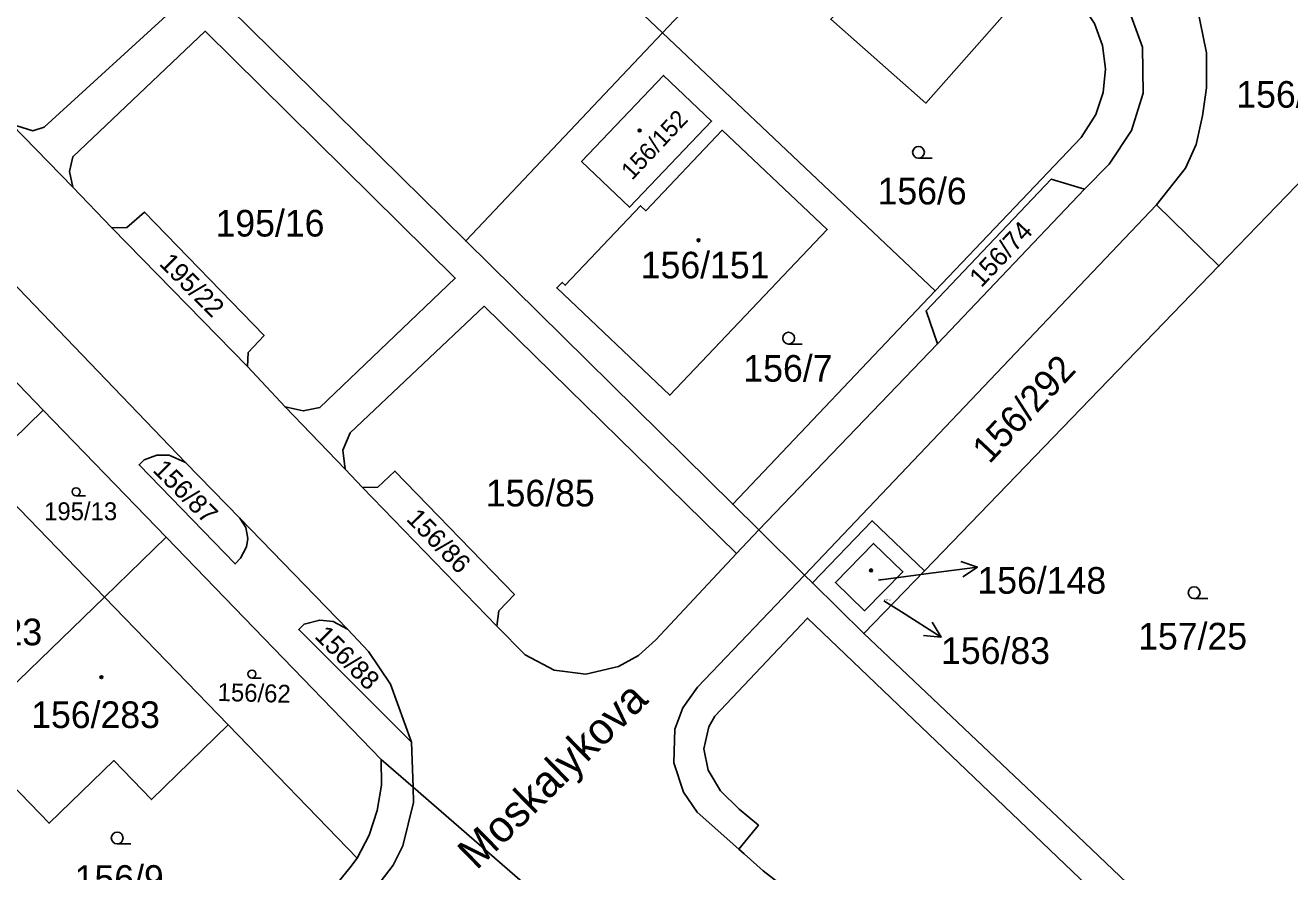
# Model space of a CAD drawing. Extents: x -598233 to -596890, y -1157848 to -1156431.
# Drawn here: x -597711.3 to -597630.6, y -1156695.2 to -1156641.2 of the extents above; entities that cross this region are included whole.
import ezdxf

# ---------------------------------------------------------------- set-up
doc = ezdxf.new("R2010")
doc.units = 0
for name, color, linetype in [('Level 1', 7, 'Continuous'), ('Level 11', 7, 'Continuous'), ('Level 4', 7, 'Continuous'), ('Level 5', 7, 'Continuous'), ('Level 57', 7, 'Continuous'), ('Level 60', 7, 'Continuous')]:
    doc.layers.add(name, color=color, linetype=linetype)

msp = doc.modelspace()

# ---------------------------------------------------------------- linework, layer by layer
at = {"layer": 'Level 1'}
for points in [[(-597670.61, -1156641.68), (-597688.79, -1156624.46)], [(-597657.3, -1156624.49), (-597643.05, -1156637.18), (-597641.03, -1156639.75), (-597639.99, -1156642.6), (-597639.94, -1156645.54), (-597640.68, -1156647.91), (-597642.12, -1156650.07), (-597643.69, -1156651.66)], [(-597712.16, -1156647.52), (-597710.81, -1156647.93), (-597710.09, -1156647.7), (-597701.55, -1156639.92), (-597715.07, -1156627.01), (-597722.85, -1156634.48), (-597723.06, -1156635.3), (-597722.83, -1156636.51)], [(-597657.42, -1156627.76), (-597670.61, -1156641.68)], [(-597653.21, -1156658.15), (-597643.9, -1156648.36), (-597642.97, -1156646.9), (-597642.49, -1156645.48), (-597642.34, -1156643.98), (-597642.53, -1156642.5), (-597643.05, -1156641.09), (-597643.87, -1156639.83), (-597656.51, -1156628.57), (-597657.42, -1156627.76)], [(-597647.47, -1156638.99), (-597653.81, -1156646.17), (-597659.88, -1156640.82), (-597659.54, -1156640.45), (-597662.02, -1156638.26), (-597656, -1156631.44), (-597647.47, -1156638.99)], [(-597639.1, -1156652.66), (-597637.24, -1156650.31), (-597636.57, -1156648.8), (-597636.16, -1156646.98), (-597635.89, -1156645.2), (-597635.91, -1156642.95), (-597636.5, -1156640.05), (-597637.79, -1156637.25), (-597639.98, -1156634.55), (-597640.57, -1156633.94)], [(-597700.93, -1156637.45), (-597694.23, -1156644.06), (-597683.18, -1156654.96)], [(-597694.71, -1156665.55), (-597693.55, -1156665.81), (-597692.48, -1156665.59), (-597683.84, -1156657.34), (-597699.81, -1156641.58), (-597708.26, -1156649.59), (-597708.46, -1156650.53), (-597708.25, -1156651.53)], [(-597670.61, -1156641.68), (-597683.18, -1156654.96)], [(-597653.21, -1156658.15), (-597670.61, -1156641.68)], [(-597675.78, -1156649.9), (-597670.55, -1156644.4), (-597667.49, -1156647.31), (-597672.72, -1156652.81), (-597675.78, -1156649.9)], [(-597635.11, -1156656.56), (-597624, -1156645.06)], [(-597708.25, -1156651.53), (-597712.16, -1156647.52)], [(-597666.8, -1156647.9), (-597660.1, -1156654.23), (-597670.16, -1156664.81), (-597677.37, -1156657.96), (-597677.02, -1156657.61), (-597676.83, -1156657.79), (-597672.02, -1156652.72), (-597671.69, -1156653.04), (-597666.8, -1156647.9)], [(-597643.69, -1156651.66), (-597645.81, -1156651.01), (-597653.8, -1156659.42), (-597653.07, -1156661.53)], [(-597708.25, -1156651.53), (-597705.77, -1156654.13)], [(-597653.07, -1156661.53), (-597643.69, -1156651.66)], [(-597661.55, -1156676.28), (-597639.1, -1156652.66)], [(-597639.1, -1156652.66), (-597635.11, -1156656.56)], [(-597705.77, -1156654.13), (-597704.81, -1156654.11), (-597703.68, -1156653.12), (-597696.04, -1156660.99), (-597697.06, -1156662.08), (-597697.1, -1156662.97)], [(-597705.77, -1156654.13), (-597697.1, -1156662.97)], [(-597683.18, -1156654.96), (-597666.14, -1156671.76)], [(-597713.26, -1156656.43), (-597701.06, -1156669.09)], [(-597635.11, -1156656.56), (-597653.9, -1156676.01)], [(-597717.99, -1156657.66), (-597713.34, -1156662.46), (-597710.15, -1156665.76)], [(-597666.14, -1156671.76), (-597653.21, -1156658.15)], [(-597690.87, -1156669.53), (-597691.01, -1156668.31), (-597690.55, -1156667.2), (-597682.01, -1156659.13), (-597665.89, -1156674.9)], [(-597664.48, -1156673.4), (-597653.07, -1156661.53)], [(-597697.1, -1156662.97), (-597694.71, -1156665.55)], [(-597710.15, -1156665.76), (-597714.09, -1156669.58)], [(-597710.15, -1156665.76), (-597702.93, -1156673.21), (-597702.3, -1156673.86)], [(-597690.87, -1156669.53), (-597694.71, -1156665.55)], [(-597701.06, -1156669.09), (-597702.1, -1156668.64), (-597702.88, -1156668.64), (-597703.69, -1156668.92), (-597704.02, -1156669.24), (-597697.9, -1156675.57), (-597697.55, -1156675.2), (-597697.16, -1156674.47), (-597697.08, -1156673.94), (-597697.22, -1156673.25), (-597697.6, -1156672.65)], [(-597697.6, -1156672.65), (-597701.06, -1156669.09)], [(-597714.09, -1156669.58), (-597706.24, -1156677.68)], [(-597689.77, -1156670.69), (-597690.87, -1156669.53)], [(-597681.19, -1156679.54), (-597681.06, -1156678.56), (-597680.07, -1156677.53), (-597687.7, -1156669.65), (-597688.78, -1156670.67), (-597689.77, -1156670.69)], [(-597689.77, -1156670.69), (-597681.19, -1156679.54)], [(-597664.48, -1156673.4), (-597666.14, -1156671.76)], [(-597697.6, -1156672.65), (-597690.72, -1156679.74)], [(-597653.9, -1156676.01), (-597657.24, -1156672.81), (-597661.05, -1156676.78)], [(-597706.24, -1156677.68), (-597702.3, -1156673.86)], [(-597688.58, -1156688.04), (-597702.3, -1156673.86)], [(-597664.48, -1156673.4), (-597665.89, -1156674.9)], [(-597664.48, -1156673.4), (-597661.55, -1156676.28)], [(-597659.58, -1156676.75), (-597657.16, -1156674.26), (-597655.27, -1156676.07), (-597657.72, -1156678.56), (-597659.58, -1156676.75)], [(-597665.89, -1156674.9), (-597671.04, -1156680.41), (-597672.16, -1156681.42), (-597673.43, -1156682.12), (-597675.52, -1156682.61), (-597677.54, -1156682.35), (-597679.38, -1156681.36), (-597681.19, -1156679.54)], [(-597665.74, -1156693.77), (-597668.41, -1156691.41), (-597669.27, -1156690.13), (-597669.9, -1156688.27), (-597669.83, -1156686.12), (-597669.33, -1156684.75), (-597668.39, -1156683.44), (-597661.55, -1156676.28)], [(-597661.55, -1156676.28), (-597661.05, -1156676.78)], [(-597657.77, -1156680.01), (-597653.9, -1156676.01)], [(-597661.05, -1156676.78), (-597657.77, -1156680.01)], [(-597706.24, -1156677.68), (-597715.16, -1156686.32)], [(-597706.24, -1156677.68), (-597698.34, -1156685.84)], [(-597690.72, -1156679.74), (-597691.63, -1156679.25), (-597692.49, -1156679.15), (-597693.49, -1156679.41), (-597693.83, -1156679.76), (-597686.63, -1156686.94)], [(-597665.74, -1156693.77), (-597664.5, -1156692.24), (-597665.72, -1156691.21), (-597666.91, -1156690.05), (-597667.7, -1156688.72), (-597667.97, -1156687.36), (-597667.66, -1156685.97), (-597667.27, -1156685.29), (-597661.36, -1156679.02), (-597644.95, -1156694.72), (-597630.77, -1156708.28), (-597629.1, -1156709.46), (-597631.47, -1156712.83), (-597633.06, -1156714.05), (-597634.88, -1156714.66), (-597636.41, -1156714.67), (-597638.29, -1156714.46)], [(-597686.63, -1156686.94), (-597687.98, -1156683.25), (-597689.39, -1156681.16), (-597690.72, -1156679.74)], [(-597634.18, -1156702.41), (-597644.58, -1156692.49), (-597657.77, -1156680.01)], [(-597698.34, -1156685.84), (-597703.24, -1156690.6), (-597705.64, -1156688.12), (-597709.77, -1156692.11), (-597715.27, -1156686.43)], [(-597698.34, -1156685.84), (-597690.1, -1156694.34)], [(-597686.63, -1156686.94), (-597686.53, -1156689.82)], [(-597690.1, -1156694.34), (-597689.33, -1156692.88), (-597688.82, -1156691.31), (-597688.56, -1156689.69), (-597688.58, -1156688.04)], [(-597686.53, -1156689.82), (-597688.58, -1156688.04)], [(-597686.53, -1156689.82), (-597686.5, -1156690.8), (-597687.19, -1156693.55), (-597687.81, -1156694.8), (-597689.13, -1156696.52), (-597689.98, -1156697.26), (-597690.52, -1156697.64), (-597698.5, -1156701.76), (-597699.2, -1156702.39), (-597713.49, -1156716.51), (-597714.13, -1156717.22), (-597718.64, -1156725.65), (-597719.37, -1156726.36)], [(-597678.75, -1156696.58), (-597686.53, -1156689.82)], [(-597665.74, -1156693.77), (-597665.4, -1156694.07), (-597664.19, -1156695.16), (-597662.12, -1156696.75)], [(-597690.1, -1156694.34), (-597690.58, -1156694.95), (-597691.31, -1156695.88), (-597700.52, -1156700.76), (-597705.92, -1156706.09)]]:
    msp.add_lwpolyline(points, dxfattribs=at)
at = {"layer": 'Level 5'}
for p, q in [((-597654.28, -1156649.68), (-597653.405, -1156649.68)), ((-597662.57, -1156661.54), (-597661.695, -1156661.54)), ((-597708.04, -1156671.22), (-597707.445, -1156671.22)), ((-597636.69, -1156677.78), (-597635.815, -1156677.78)), ((-597696.82, -1156682.85), (-597696.225, -1156682.85)), ((-597705.42, -1156693.43), (-597704.545, -1156693.43))]:
    msp.add_line(p, q, dxfattribs=at)
for centre, radius in [((-597672.08, -1156647.92), 0.09), ((-597672.08, -1156647.92), 0.0521), ((-597654.28, -1156649.305), 0.375), ((-597668.32, -1156654.92), 0.09), ((-597668.32, -1156654.92), 0.0521), ((-597662.57, -1156661.165), 0.375), ((-597708.04, -1156670.965), 0.255), ((-597657.31, -1156675.98), 0.09), ((-597657.31, -1156675.98), 0.0521), ((-597636.69, -1156677.405), 0.375), ((-597706.43, -1156682.8), 0.09), ((-597706.43, -1156682.8), 0.0521), ((-597696.82, -1156682.595), 0.255), ((-597705.42, -1156693.055), 0.375)]:
    msp.add_circle(centre, radius, dxfattribs=at)
at = {"layer": 'Level 57'}
for p, q in [((-597656.83, -1156676.6), (-597653.495, -1156676.161)), ((-597653.495, -1156676.161), (-597650.521, -1156675.77)), ((-597656.49, -1156677.92), (-597655.369, -1156678.636)), ((-597655.369, -1156678.636), (-597652.84, -1156680.25))]:
    msp.add_line(p, q, dxfattribs=at)
for points in [[(-597651.577, -1156675.404), (-597650.521, -1156675.77), (-597651.447, -1156676.396)], [(-597653.414, -1156679.291), (-597652.84, -1156680.25), (-597653.952, -1156680.134)]]:
    msp.add_lwpolyline(points, dxfattribs=at)
at = {"layer": 'Level 60'}
for points in [[(-597688.79, -1156624.46), (-597676.22, -1156611.01), (-597667.83, -1156618.49), (-597657.42, -1156627.76), (-597670.61, -1156641.68)], [(-597670.61, -1156641.68), (-597683.18, -1156654.96), (-597694.23, -1156644.06), (-597700.93, -1156637.45), (-597688.79, -1156624.46)], [(-597710.81, -1156647.93), (-597712.16, -1156647.52), (-597713.12, -1156646.46), (-597713.16, -1156645.57), (-597712.04, -1156644.47), (-597719.71, -1156636.63), (-597720.83, -1156637.54), (-597721.77, -1156637.59), (-597722.83, -1156636.51), (-597723.06, -1156635.3), (-597722.85, -1156634.48), (-597715.07, -1156627.01), (-597701.55, -1156639.92), (-597710.09, -1156647.7)], [(-597643.9, -1156648.36), (-597653.21, -1156658.15), (-597670.61, -1156641.68), (-597657.42, -1156627.76), (-597656.51, -1156628.57), (-597643.87, -1156639.83), (-597643.05, -1156641.09), (-597642.53, -1156642.5), (-597642.34, -1156643.98), (-597642.49, -1156645.48), (-597642.97, -1156646.9)], [(-597647.47, -1156638.99), (-597653.81, -1156646.17), (-597659.88, -1156640.82), (-597659.54, -1156640.45), (-597662.02, -1156638.26), (-597656, -1156631.44)], [(-597653.81, -1156646.17), (-597647.47, -1156638.99), (-597656, -1156631.44), (-597662.02, -1156638.26), (-597659.54, -1156640.45), (-597659.88, -1156640.82)], [(-597640.57, -1156633.94), (-597638.46, -1156631.57), (-597630.41, -1156638.74), (-597624, -1156645.06), (-597635.11, -1156656.56), (-597639.1, -1156652.66), (-597637.24, -1156650.31), (-597636.57, -1156648.8), (-597636.16, -1156646.98), (-597635.89, -1156645.2), (-597635.91, -1156642.95), (-597636.5, -1156640.05), (-597637.79, -1156637.25), (-597639.98, -1156634.55)], [(-597693.55, -1156665.81), (-597694.71, -1156665.55), (-597697.1, -1156662.97), (-597697.06, -1156662.08), (-597696.04, -1156660.99), (-597703.68, -1156653.12), (-597704.81, -1156654.11), (-597705.77, -1156654.13), (-597708.25, -1156651.53), (-597708.46, -1156650.53), (-597708.26, -1156649.59), (-597699.81, -1156641.58), (-597683.84, -1156657.34), (-597692.48, -1156665.59)], [(-597653.21, -1156658.15), (-597666.14, -1156671.76), (-597683.18, -1156654.96), (-597670.61, -1156641.68)], [(-597675.78, -1156649.9), (-597670.55, -1156644.4), (-597667.49, -1156647.31), (-597672.72, -1156652.81)], [(-597670.55, -1156644.4), (-597675.78, -1156649.9), (-597672.72, -1156652.81), (-597667.49, -1156647.31)], [(-597666.8, -1156647.9), (-597660.1, -1156654.23), (-597670.16, -1156664.81), (-597677.37, -1156657.96), (-597677.02, -1156657.61), (-597676.83, -1156657.79), (-597672.02, -1156652.72), (-597671.69, -1156653.04)], [(-597660.1, -1156654.23), (-597666.8, -1156647.9), (-597671.69, -1156653.04), (-597672.02, -1156652.72), (-597676.83, -1156657.79), (-597677.02, -1156657.61), (-597677.37, -1156657.96), (-597670.16, -1156664.81)], [(-597645.81, -1156651.01), (-597643.69, -1156651.66), (-597653.07, -1156661.53), (-597653.8, -1156659.42)], [(-597639.1, -1156652.66), (-597635.11, -1156656.56), (-597653.9, -1156676.01), (-597657.24, -1156672.81), (-597661.05, -1156676.78), (-597661.55, -1156676.28)], [(-597705.77, -1156654.13), (-597704.81, -1156654.11), (-597703.68, -1156653.12), (-597696.04, -1156660.99), (-597697.06, -1156662.08), (-597697.1, -1156662.97)], [(-597721.93, -1156661.48), (-597717.99, -1156657.66), (-597713.34, -1156662.46), (-597710.15, -1156665.76), (-597714.09, -1156669.58), (-597716.51, -1156667.08)], [(-597665.89, -1156674.9), (-597671.04, -1156680.41), (-597672.16, -1156681.42), (-597673.43, -1156682.12), (-597675.52, -1156682.61), (-597677.54, -1156682.35), (-597679.38, -1156681.36), (-597681.19, -1156679.54), (-597681.06, -1156678.56), (-597680.07, -1156677.53), (-597687.7, -1156669.65), (-597688.78, -1156670.67), (-597689.77, -1156670.69), (-597690.87, -1156669.53), (-597691.01, -1156668.31), (-597690.55, -1156667.2), (-597682.01, -1156659.13)], [(-597702.3, -1156673.86), (-597706.24, -1156677.68), (-597714.09, -1156669.58), (-597710.15, -1156665.76), (-597702.93, -1156673.21)], [(-597702.1, -1156668.64), (-597701.06, -1156669.09), (-597697.6, -1156672.65), (-597697.22, -1156673.25), (-597697.08, -1156673.94), (-597697.16, -1156674.47), (-597697.55, -1156675.2), (-597697.9, -1156675.57), (-597704.02, -1156669.24), (-597703.69, -1156668.92), (-597702.88, -1156668.64)], [(-597716.48, -1156676.83), (-597718.97, -1156674.32), (-597714.09, -1156669.58), (-597706.24, -1156677.68), (-597715.16, -1156686.32), (-597720.56, -1156680.77)], [(-597681.06, -1156678.56), (-597681.19, -1156679.54), (-597689.77, -1156670.69), (-597688.78, -1156670.67), (-597687.7, -1156669.65), (-597680.07, -1156677.53)], [(-597657.77, -1156680.01), (-597661.05, -1156676.78), (-597657.24, -1156672.81), (-597653.9, -1156676.01)], [(-597706.24, -1156677.68), (-597702.3, -1156673.86), (-597688.58, -1156688.04), (-597688.56, -1156689.69), (-597688.82, -1156691.31), (-597689.33, -1156692.88), (-597690.1, -1156694.34), (-597698.34, -1156685.84)], [(-597659.58, -1156676.75), (-597657.16, -1156674.26), (-597655.27, -1156676.07), (-597657.72, -1156678.56)], [(-597657.16, -1156674.26), (-597659.58, -1156676.75), (-597657.72, -1156678.56), (-597655.27, -1156676.07)], [(-597698.34, -1156685.84), (-597703.24, -1156690.6), (-597705.64, -1156688.12), (-597709.77, -1156692.11), (-597715.27, -1156686.43), (-597715.16, -1156686.32), (-597706.24, -1156677.68)], [(-597691.63, -1156679.25), (-597690.72, -1156679.74), (-597689.39, -1156681.16), (-597687.98, -1156683.25), (-597686.63, -1156686.94), (-597693.83, -1156679.76), (-597693.49, -1156679.41), (-597692.49, -1156679.15)], [(-597691.31, -1156695.88), (-597700.52, -1156700.76), (-597705.92, -1156706.09), (-597714.33, -1156697.41), (-597720.28, -1156691.27), (-597715.27, -1156686.43), (-597709.77, -1156692.11), (-597705.64, -1156688.12), (-597703.24, -1156690.6), (-597698.34, -1156685.84), (-597690.1, -1156694.34), (-597690.58, -1156694.95)]]:
    msp.add_lwpolyline(points, close=True, dxfattribs=at)
for points in [[(-597716.2, -1156622.99), (-597700.93, -1156637.45), (-597694.23, -1156644.06), (-597683.18, -1156654.96), (-597666.14, -1156671.76), (-597664.48, -1156673.4), (-597665.89, -1156674.9), (-597682.01, -1156659.13), (-597690.55, -1156667.2), (-597691.01, -1156668.31), (-597690.87, -1156669.53), (-597694.71, -1156665.55), (-597693.55, -1156665.81), (-597692.48, -1156665.59), (-597683.84, -1156657.34), (-597699.81, -1156641.58), (-597708.26, -1156649.59), (-597708.46, -1156650.53), (-597708.25, -1156651.53), (-597712.16, -1156647.52), (-597710.81, -1156647.93), (-597710.09, -1156647.7), (-597701.55, -1156639.92), (-597715.07, -1156627.01)], [(-597641.03, -1156639.75), (-597639.99, -1156642.6), (-597639.94, -1156645.54), (-597640.68, -1156647.91), (-597642.12, -1156650.07), (-597643.69, -1156651.66), (-597645.81, -1156651.01), (-597653.8, -1156659.42), (-597653.07, -1156661.53), (-597664.48, -1156673.4), (-597666.14, -1156671.76), (-597653.21, -1156658.15), (-597643.9, -1156648.36), (-597642.97, -1156646.9), (-597642.49, -1156645.48), (-597642.34, -1156643.98), (-597642.53, -1156642.5), (-597643.05, -1156641.09)], [(-597636.5, -1156640.05), (-597635.91, -1156642.95), (-597635.89, -1156645.2), (-597636.16, -1156646.98), (-597636.57, -1156648.8), (-597637.24, -1156650.31), (-597639.1, -1156652.66), (-597661.55, -1156676.28), (-597664.48, -1156673.4), (-597653.07, -1156661.53), (-597643.69, -1156651.66), (-597642.12, -1156650.07), (-597640.68, -1156647.91), (-597639.94, -1156645.54), (-597639.99, -1156642.6), (-597641.03, -1156639.75)], [(-597634.18, -1156702.41), (-597644.58, -1156692.49), (-597657.77, -1156680.01), (-597653.9, -1156676.01), (-597635.11, -1156656.56), (-597624, -1156645.06)], [(-597712.16, -1156647.52), (-597708.25, -1156651.53), (-597705.77, -1156654.13), (-597697.1, -1156662.97), (-597694.71, -1156665.55), (-597690.87, -1156669.53), (-597689.77, -1156670.69), (-597681.19, -1156679.54), (-597679.38, -1156681.36), (-597677.54, -1156682.35), (-597675.52, -1156682.61), (-597673.43, -1156682.12), (-597672.16, -1156681.42), (-597671.04, -1156680.41), (-597665.89, -1156674.9), (-597664.48, -1156673.4), (-597661.55, -1156676.28), (-597668.39, -1156683.44), (-597669.33, -1156684.75), (-597669.83, -1156686.12), (-597669.9, -1156688.27), (-597669.27, -1156690.13), (-597668.41, -1156691.41), (-597665.74, -1156693.77), (-597665.4, -1156694.07), (-597664.19, -1156695.16), (-597662.12, -1156696.75)], [(-597713.26, -1156656.43), (-597701.06, -1156669.09), (-597702.1, -1156668.64), (-597702.88, -1156668.64), (-597703.69, -1156668.92), (-597704.02, -1156669.24), (-597697.9, -1156675.57), (-597697.55, -1156675.2), (-597697.16, -1156674.47), (-597697.08, -1156673.94), (-597697.22, -1156673.25), (-597697.6, -1156672.65), (-597690.72, -1156679.74), (-597691.63, -1156679.25), (-597692.49, -1156679.15), (-597693.49, -1156679.41), (-597693.83, -1156679.76), (-597686.63, -1156686.94), (-597686.53, -1156689.82), (-597688.58, -1156688.04), (-597702.3, -1156673.86), (-597702.93, -1156673.21), (-597710.15, -1156665.76), (-597713.34, -1156662.46)], [(-597678.75, -1156696.58), (-597686.53, -1156689.82), (-597686.63, -1156686.94), (-597687.98, -1156683.25), (-597689.39, -1156681.16), (-597690.72, -1156679.74), (-597697.6, -1156672.65), (-597701.06, -1156669.09), (-597713.26, -1156656.43)], [(-597665.72, -1156691.21), (-597664.5, -1156692.24), (-597665.74, -1156693.77), (-597668.41, -1156691.41), (-597669.27, -1156690.13), (-597669.9, -1156688.27), (-597669.83, -1156686.12), (-597669.33, -1156684.75), (-597668.39, -1156683.44), (-597661.55, -1156676.28), (-597661.05, -1156676.78), (-597657.77, -1156680.01), (-597644.58, -1156692.49), (-597634.18, -1156702.41)], [(-597630.77, -1156708.28), (-597644.95, -1156694.72), (-597661.36, -1156679.02), (-597667.27, -1156685.29), (-597667.66, -1156685.97), (-597667.97, -1156687.36), (-597667.7, -1156688.72), (-597666.91, -1156690.05), (-597665.72, -1156691.21)], [(-597662.12, -1156696.75), (-597664.19, -1156695.16), (-597665.4, -1156694.07), (-597665.74, -1156693.77), (-597664.5, -1156692.24), (-597665.72, -1156691.21), (-597666.91, -1156690.05), (-597667.7, -1156688.72), (-597667.97, -1156687.36), (-597667.66, -1156685.97), (-597667.27, -1156685.29), (-597661.36, -1156679.02), (-597644.95, -1156694.72), (-597630.77, -1156708.28)], [(-597715.17, -1156715.23), (-597705.92, -1156706.09), (-597700.52, -1156700.76), (-597691.31, -1156695.88), (-597690.58, -1156694.95), (-597690.1, -1156694.34), (-597689.33, -1156692.88), (-597688.82, -1156691.31), (-597688.56, -1156689.69), (-597688.58, -1156688.04), (-597686.53, -1156689.82), (-597686.5, -1156690.8), (-597687.19, -1156693.55), (-597687.81, -1156694.8), (-597689.13, -1156696.52), (-597689.98, -1156697.26), (-597690.52, -1156697.64), (-597698.5, -1156701.76), (-597699.2, -1156702.39), (-597713.49, -1156716.51)], [(-597713.49, -1156716.51), (-597699.2, -1156702.39), (-597698.5, -1156701.76), (-597690.52, -1156697.64), (-597689.98, -1156697.26), (-597689.13, -1156696.52), (-597687.81, -1156694.8), (-597687.19, -1156693.55), (-597686.5, -1156690.8), (-597686.53, -1156689.82), (-597678.75, -1156696.58), (-597679.19, -1156696.78), (-597681.14, -1156698.43), (-597683.93, -1156701.31), (-597730.11, -1156746.9)]]:
    msp.add_lwpolyline(points, dxfattribs=at)

# ---------------------------------------------------------------- texts
at = {"layer": 'Level 11'}
msp.add_text('Moskalykova', height=2, rotation=44.38883, dxfattribs=at).set_placement((-597682.481, -1156695.157))
at = {"layer": 'Level 4'}
for s, height, p in [('156/291', 1.7, (-597633.998, -1156646.46)), ('156/6', 1.7, (-597656.894, -1156652.63)), ('195/16', 1.7, (-597699.145, -1156654.68)), ('156/151', 1.7, (-597672.007, -1156657.35)), ('156/7', 1.7, (-597665.458, -1156663.94)), ('156/85', 1.7, (-597681.897, -1156671.9)), ('195/13', 1.14, (-597710.084, -1156672.78)), ('156/148', 0.1, (-597656.83, -1156676.6)), ('156/83', 0.1, (-597656.49, -1156677.92)), ('195/23', 1.7, (-597717.16, -1156680.76)), ('157/25', 1.7, (-597640.263, -1156681.03)), ('156/283', 1.7, (-597710.91, -1156686.04)), ('156/9', 1.7, (-597708.134, -1156696.49))]:
    msp.add_text(s, height=height, dxfattribs=at).set_placement(p)
for s, height, rotation, p in [('156/152', 1.1, 46.8, (-597672.56, -1156651.13)), ('156/74', 1.2, 46.8, (-597650.274, -1156657.989)), ('195/22', 1.2, 315, (-597702.8, -1156656.46)), ('156/292', 1.7, 46.89153, (-597649.759, -1156669.24)), ('156/87', 1.2, 315, (-597703.209, -1156669.641)), ('156/86', 1.2, 314.1, (-597687.03, -1156672.747)), ('156/88', 1.2, 315, (-597692.885, -1156680.235)), ('156/62', 1.14, 358.5024, (-597699.02, -1156684.31))]:
    msp.add_text(s, height=height, rotation=rotation, dxfattribs=at).set_placement(p)
at = {"layer": 'Level 57'}
for s, p in [('156/148', (-597650.521, -1156677.47)), ('156/83', (-597652.84, -1156681.95))]:
    msp.add_text(s, height=1.7, dxfattribs=at).set_placement(p)

doc.saveas('drawing.dxf')
